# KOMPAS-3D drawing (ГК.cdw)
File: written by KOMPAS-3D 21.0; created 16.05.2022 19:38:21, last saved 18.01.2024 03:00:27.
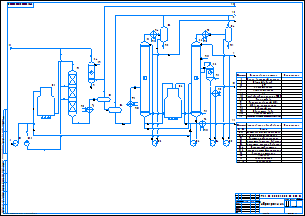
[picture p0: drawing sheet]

Sheet 1: A1, landscape

Document properties: Автор: 79870418100; Полное имя файла: C:\Users\nikit\Desktop\ГКВД\ГК.cdw; Литера: У

Title block, sheet 1: Наименование: Гидрокрекинг; designation: УТЭК 00.00.00.КП.00.00.000.С3; Количество листов документа: 1; cell 10: КИПиА; Форматы листов документа: A1; stored path: C:\Users\79870\Desktop\Ахметнабиев.cdw

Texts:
  ЦК1
  VIII
  XII
  VII
  XIII
  XIV
  III
  Наименование потока
  Сырье вакуумный газоиль
  Свежий водород
  Легкий бензин
  Тяжелый бензин
  Углеводородные газы на ГФУ
  Газы отдува
  Регенерированный МЭА
  МЭА на регенерацию
  Водянной пар
  Оборотная вода
  Теплоноситель
  Конденсат в закрытую систему дренирования
  Наименование оборудования
  Насос
  Центробежный компрессор
  Печь цилиндрическая
  Реактор гидрокрекинга
  Сепаратор высокого давления
  Сепаратор низкого давления
  Бензиноотделитель
  Колонны ректификационные
  Колонна отпарная
  Абсорбер
  Теплообменик
  Холодильник
Dimensions and other numbers on the sheet: 1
